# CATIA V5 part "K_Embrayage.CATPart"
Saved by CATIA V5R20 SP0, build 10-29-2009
Part number: Embrayage
Bounding box of the stored display mesh (mm): x -160 to 160, y -110 to -95, z -160 to 160
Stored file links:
  G:\Khaled_CFAO_2011\ST2M\ST2M_GR1\mponsin\Khaled\CAD_ThinkMOTION\K_Embrayage.CATPart
  C:\Users\Socar\Documents\thinkmotion\Final\Diff2.CATProduct
  G:\Khaled_CFAO_2011\ST2M\ST2M_GR1\mponsin\Khaled\CAD_ThinkMOTION\K_mponsin.CATProduct
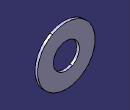
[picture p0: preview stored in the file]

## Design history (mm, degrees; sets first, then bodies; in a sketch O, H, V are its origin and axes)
External parameters (linked from other documents)
  `External.Rint embrayage` = 70 mm
  `External.R interne` = 160 mm
Set1
  Plane1 "interface visco/embrayage": linked copy from another document
  Plane2 "disques/V": linked copy from another document
  Line1 "axe general": linked copy from another document
Body1 (main body)
  Sketch1 on yz-plane, origin (0, 0, 0), H (0, 1, 0), V (0, 0, 1)
    line L1 (-110, 160) -> (-95, 160)
    line L2 (-95, 160) -> (-95, 72)
    line L3 (-95, 72) -> (-110, 72)
    line L4 (-110, 72) -> (-110, 160)
    reference intersected line E1 through (-110, 0) direction (0, 1) from Plane1
    reference intersected line E2 through (-95, 0) direction (0, 1) from Plane2
    distance L3 H = 72 {= `External.Rint embrayage` +2mm}
    distance L1 H = 160 {= `External.R interne`}
    horizontal: L1 H, L3 H
    vertical: L2 V, L4 V
    coincidence: L4 E1, E2 L2
  Shaft1: profile Sketch1, axis Line1, angle 360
